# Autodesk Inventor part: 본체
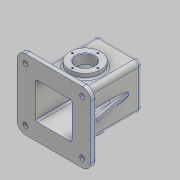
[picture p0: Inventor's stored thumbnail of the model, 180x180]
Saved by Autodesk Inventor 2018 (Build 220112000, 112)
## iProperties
Created: 2022-11
Part Number: 본체
Material: 알루미늄 6061
Document SubType Name: Modeling
Designer: home
Density: 2.7 g/cm^3
Appearance: 알루미늄 - 평지
Mass: 1126.74 g
Surface Area: 1013.84 cm^2
Volume: 417.312 cm^3
Author: home
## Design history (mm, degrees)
sketch "스케치1"
  geometry: L1 (-65, 47)-(-65, -47); L2 (-50, -62)-(50, -62); L3 (65, -47)-(65, 47); L4 (50, 62)-(-50, 62); L5 (-65, 62)-(65, -62); L6 (-65, -62)-(65, 62); A1 r 15 centre (50, 47) between (65, 47) and (50, 62); A2 r 15 centre (-50, 47) between (-50, 62) and (-65, 47); A3 r 15 centre (-50, -47) between (-65, -47) and (-50, -62); A4 r 15 centre (50, -47) between (50, -62) and (65, -47); 1 further point
  constraints: 12 end point, 8 point on circle, 8 point on line, 8 tangent, 4 centre point, 3 equal radius, 2 midpoint, 2 parallel, 1 perpendicular, 1 vertical
  dimensions: "d0" = 124 distance of L5.start L6.start; "d1" = 130 distance of L5.end L6.start; "d4" = 15 radius of A1
extrude "돌출1" new body sketch "스케치1" distance "d2" = 10; taper "d3" = 0 deg
sketch "스케치3"
  geometry: C1 r 4.5 at (-50, -47); C2 r 4.5 at (50, -47); C3 r 4.5 at (50, 47); C4 r 4.5 at (-50, 47); A1 r 15 centre (-50, -47) between (-65, -47) and (-50, -62) reference; A2 r 15 centre (50, -47) between (50, -62) and (65, -47) reference; A3 r 15 centre (50, 47) between (65, 47) and (50, 62) reference; A4 r 15 centre (-50, 47) between (-50, 62) and (-65, 47) reference; 1 further point
  constraints: 4 centre point, 4 coincident
  dimensions: "d5" = 9 diameter of C1; "d6" = 9 diameter of C2; "d7" = 9 diameter of C3; "d8" = 9 diameter of C4
extrude "돌출2" cut sketch "스케치3" extent not by distance; stored distance "d9" = 10; taper "d10" = 0 deg
sketch "스케치4"
  geometry: L1 (40, -40)-(40, 40); L2 (40, 40)-(-40, 40); L3 (-40, 40)-(-40, -40); L4 (-40, -40)-(40, -40); L5 (40, -40)-(-40, 40); L6 (40, 40)-(-40, -40); 1 further point
  constraints: 12 end point, 2 midpoint, 2 parallel, 1 perpendicular, 1 vertical
  dimensions: "d11" = 80 distance of L1.start L1.end; "d12" = 80 distance of L2.end L1.end
extrude "돌출3" join sketch "스케치4" distance "d13" = 107; taper "d14" = 0 deg
sketch "스케치5"
  geometry: C1 r 20 at (0, 0); 1 further point
  constraints: 1 centre point, 1 coincident
  dimensions: "d15" = 40 diameter of C1
extrude "돌출4" join sketch "스케치5" distance "d16" = 10; taper "d17" = -10 deg
sketch "스케치6"
  geometry: C1 r 20 at (0, 0) reference; C2 r 14 at (0, 0); 1 further point
  constraints: 1 centre point, 1 coincident
  dimensions: "d18" = 28 diameter of C2
extrude "돌출5" cut sketch "스케치6" distance "d19" = 4; taper "d20" = 0 deg
sketch "스케치7"
  geometry: C1 r 14 at (0, 0) reference; C2 r 10.5 at (0, 0); 1 further point
  constraints: 1 centre point, 1 coincident
  dimensions: "d21" = 21 diameter of C2
extrude "돌출6" cut sketch "스케치7" extent not by distance; stored distance "d22" = 4; taper "d23" = 0 deg
sketch "스케치8"
  geometry: L1 (40, -10)-(40, 45); C1 r 27.5 at (40, 45)
  constraints: 2 end point, 1 centre point, 1 coincident, 1 vertical
  dimensions: "d24" = 55 distance of L1.start L1.end; "d25" = 55 diameter of C1
extrude "돌출7" join sketch "스케치8" distance "d26" = 9; taper "d27" = 0 deg
sketch "스케치9" dims "d28" = 45
  geometry: C1 r 27.5 at (0, 0) reference; 3 further points
  constraints: 1 coincident, 1 vertical alignment, 2 other
  dimensions: "d72" = 77.5 distance of point (0, -55) point (0, 22.5)
hole "구멍1" sketch "스케치9" at (0, 22.5) diameter "d29" = 3.242; stored, may be unused: countersink angle "d33" = 90 deg, drill point angle "d35" = 118 deg; dims "d30" = 8, "d31" = 4, "d32" = 2, "d34" = 10
sketch "스케치10"
  geometry: C1 r 27.5 at (0, 0) reference; C2 r 16 at (0, 0); 1 further point
  constraints: 1 centre point, 1 coincident
  dimensions: "d39" = 32 diameter of C2
extrude "돌출8" cut sketch "스케치10" extent not by distance; stored distance "d40" = 9; taper "d41" = 0 deg
sketch "스케치11"
  geometry: L1 (-32, 32)-(-32, -32); L2 (-32, -32)-(32, -32); L3 (32, -32)-(32, 32); L4 (32, 32)-(-32, 32); L5 (-32, 32)-(32, -32); L6 (-32, -32)-(32, 32); 1 further point
  constraints: 12 end point, 2 midpoint, 2 parallel, 1 perpendicular, 1 vertical
  dimensions: "d42" = 64 distance of L1.start L1.end; "d43" = 64 distance of L2.end L1.end
extrude "돌출9" cut sketch "스케치11" distance "d44" = 109; taper "d45" = 0 deg
sketch "스케치12"
  geometry: L1 (55, 6.161)-(39.075, 96.478); L2 (39.075, 96.478)-(39.075, 6.161); L3 (-50, 0)-(50, 0) reference; L4 (39.075, 6.161)-(55, 6.161); L5 (65, 0)-(65, 10) reference; 1 further point
  constraints: 6 end point, 2 perpendicular
  dimensions: "d46" = 10 distance from line of L5 L1.start; "d47" = 100 deg angle of L4 L1; "d73" = 25.9254 distance between parallel lines of L2 L5; "d74" = 6.16067 distance between parallel lines of L4 L3
extrude "돌출10" join sketch "스케치12" stored distance "d48" = 10; taper "d49" = 0 deg
chamfer "모따기1" distance "d52" = 1; stored, may be unused: second distance "d53" = 2, angle "d54" = 45 deg
fillet "모깎기4" dims "d63" = 3
fillet "모깎기5" dims "d64" = 8, "d65" = 3
sketch "스케치14"
  geometry: L1 (72, -96)-(72, 0) reference; L2 (13.763, 18)-(50.237, 18) reference; 2 further points
  constraints: 1 other
  dimensions: "d68" = 40 distance from line of L1 point (32, -7); "d69" = 25 distance from line of L2 point (32, -7)
feature "엠보싱2" sketch "스케치14" dims "d0" = 124, "d1" = 130, "d4" = 15, "d6" = 9, "d66" = 0.5, "d67" = 0
fillet "모깎기6" dims "d70" = 3
fillet "모깎기7" dims "d71" = 3
node "솔리드1"
pattern_circular "원형 패턴1" dims angle "d37" = 360 deg
mirror "미러2"
mirror "미러3"
